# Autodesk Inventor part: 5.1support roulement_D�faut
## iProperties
Created: 2011-01
Part Number: 5.1support roulement_D�faut
Document SubType Name: Modeling
Designer: eric
Density: 1 g/cm^3
Mass: 20.8377 g
Surface Area: 157.409 cm^2
Volume: 20.8377 cm^3
Author: eric
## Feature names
1. Base1
